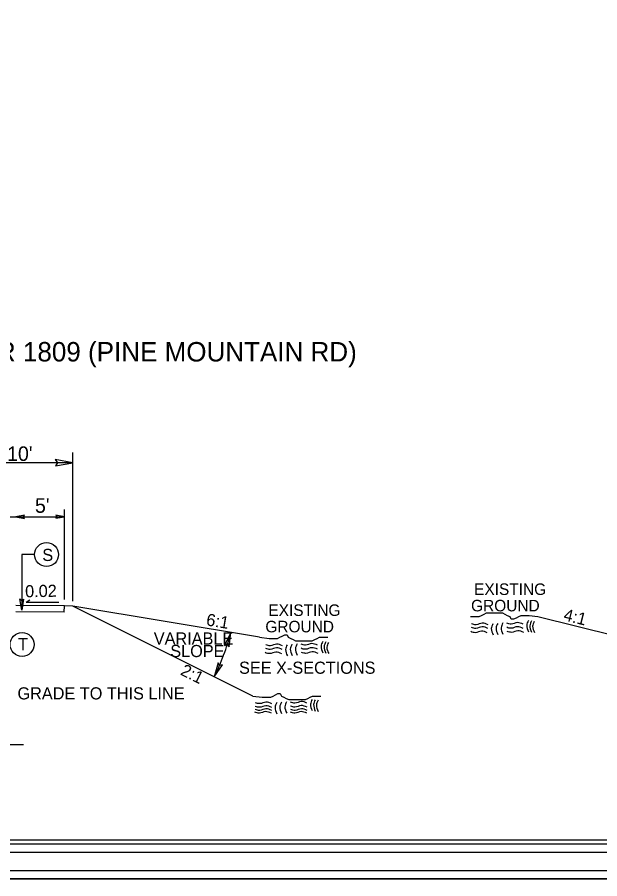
# Model space of a CAD drawing. Extents: x 2294455 to 2294795, y 719276 to 719941.
# Drawn here: x 2294590 to 2294664.8, y 719495.3 to 719606.2 of the extents above; entities that cross this region are included whole.
import ezdxf

# ---------------------------------------------------------------- set-up
doc = ezdxf.new("R2010")
doc.units = 0
for name, color, linetype in [('Default', 7, 'Continuous'), ('Old_Level_1', 7, 'Continuous'), ('Old_Level_11', 7, 'Continuous'), ('Old_Level_2', 7, 'Continuous'), ('Old_Level_3', 7, 'Continuous'), ('Sheet Cutting Line CELL', 7, 'Continuous'), ('Sheet Plot Border Inside CELL', 7, 'Continuous'), ('Sheet Plot Border Outside CELL', 7, 'Continuous'), ('Sheet Typical CELL', 7, 'Continuous'), ('Typical Hinge Slope Arterial CELL', 7, 'Continuous'), ('Typical ID Circle CELL', 7, 'Continuous'), ('Typical Terminator CELL', 7, 'Continuous'), ('Typical Text ID Circle CELL', 7, 'Continuous')]:
    doc.layers.add(name, color=color, linetype=linetype)

msp = doc.modelspace()

# ---------------------------------------------------------------- linework, layer by layer
at = {"layer": 'Default'}
msp.add_lwpolyline([(2294454.52, 719715.33), (2294794.52, 719715.33), (2294794.52, 719495.33), (2294454.52, 719495.33)], close=True, dxfattribs=at)
at = {"layer": 'Old_Level_1'}
for p, q in [((2294596.03, 719530.45), (2294589.78, 719530.49)), ((2294591.09, 719530.91), (2294591.59, 719531.22)), ((2294591.09, 719530.91), (2294595.3, 719530.91)), ((2294596.01, 719529.62), (2294596.03, 719530.45)), ((2294597.1, 719530.4), (2294596.03, 719530.45)), ((2294620.23, 719518.84), (2294597.1, 719530.4)), ((2294596.01, 719529.62), (2294589.78, 719529.66))]:
    msp.add_line(p, q, dxfattribs=at)
at = {"layer": 'Old_Level_11'}
for p, q in [((2294597.1, 719531.06), (2294597.1, 719550.17)), ((2294597.11, 719548.86), (2294581.48, 719548.86)), ((2294596.03, 719531.27), (2294596.03, 719542.83)), ((2294583.98, 719541.89), (2294596.03, 719541.89)), ((2294590.78, 719512.58), (2294528.76, 719512.58))]:
    msp.add_line(p, q, dxfattribs=at)
for points in [[(2294594.86, 719548.47), (2294597.11, 719548.86), (2294594.85, 719549.26), (2294595.14, 719548.86)], [(2294590.91, 719542.09), (2294589.78, 719541.89), (2294590.91, 719541.69), (2294590.77, 719541.89)], [(2294594.91, 719541.7), (2294596.03, 719541.89), (2294594.9, 719542.09), (2294595.05, 719541.89)], [(2294617.2, 719525.16), (2294617.41, 719527.02), (2294616.58, 719525.33), (2294616.96, 719525.46)], [(2294615.77, 719523.12), (2294615.28, 719521.32), (2294616.35, 719522.86), (2294615.96, 719522.78)]]:
    msp.add_lwpolyline(points, close=True, dxfattribs=at)
at = {"layer": 'Old_Level_2'}
for points in [[(2294650.48, 719528), (2294649.73, 719528.21), (2294648.94, 719528.01), (2294648.36, 719528.13)], [(2294650.48, 719528), (2294649.73, 719528.21), (2294648.94, 719528.01), (2294648.36, 719528.13)], [(2294651.1, 719528.14), (2294650.89, 719527.52), (2294651.12, 719526.7)], [(2294651.71, 719528.19), (2294651.5, 719527.57), (2294651.72, 719526.75)], [(2294652.36, 719528.24), (2294652.16, 719527.62), (2294652.38, 719526.8)], [(2294652.36, 719528.24), (2294652.16, 719527.62), (2294652.38, 719526.8)], [(2294654.99, 719528.07), (2294654.24, 719528.28), (2294653.45, 719528.08), (2294652.88, 719528.21)], [(2294654.99, 719528.07), (2294654.24, 719528.28), (2294653.45, 719528.08), (2294652.88, 719528.21)], [(2294655.66, 719528.55), (2294655.44, 719527.93), (2294655.67, 719527.11)], [(2294655.66, 719528.55), (2294655.44, 719527.93), (2294655.67, 719527.11)], [(2294656.05, 719528.51), (2294655.84, 719527.89), (2294656.07, 719527.06)], [(2294656.05, 719528.51), (2294655.84, 719527.89), (2294656.07, 719527.06)], [(2294656.41, 719528.44), (2294656.2, 719527.82), (2294656.43, 719527)], [(2294656.41, 719528.44), (2294656.2, 719527.82), (2294656.43, 719527)], [(2294650.38, 719526.98), (2294649.63, 719527.19), (2294648.84, 719526.99), (2294648.26, 719527.12)], [(2294650.38, 719526.98), (2294649.63, 719527.19), (2294648.84, 719526.99), (2294648.26, 719527.12)], [(2294650.46, 719527.52), (2294649.71, 719527.74), (2294648.92, 719527.54), (2294648.34, 719527.66)], [(2294650.46, 719527.52), (2294649.71, 719527.74), (2294648.92, 719527.54), (2294648.34, 719527.66)], [(2294655, 719527.54), (2294654.24, 719527.76), (2294653.45, 719527.55), (2294652.88, 719527.68)], [(2294655, 719527.54), (2294654.24, 719527.76), (2294653.45, 719527.55), (2294652.88, 719527.68)], [(2294655.06, 719527.02), (2294654.3, 719527.23), (2294653.51, 719527.03), (2294652.93, 719527.16)], [(2294655.06, 719527.02), (2294654.3, 719527.23), (2294653.51, 719527.03), (2294652.93, 719527.16)], [(2294624.02, 719524.82), (2294623.27, 719525.04), (2294622.48, 719524.84), (2294621.9, 719524.97)], [(2294624.02, 719524.82), (2294623.27, 719525.04), (2294622.48, 719524.84), (2294621.9, 719524.97)], [(2294624.04, 719525.3), (2294623.29, 719525.51), (2294622.5, 719525.31), (2294621.92, 719525.44)], [(2294624.04, 719525.3), (2294623.29, 719525.51), (2294622.5, 719525.31), (2294621.92, 719525.44)], [(2294624.66, 719525.44), (2294624.45, 719524.82), (2294624.68, 719524)], [(2294625.27, 719525.49), (2294625.06, 719524.87), (2294625.29, 719524.05)], [(2294625.27, 719525.49), (2294625.06, 719524.87), (2294625.29, 719524.05)], [(2294625.93, 719525.55), (2294625.72, 719524.93), (2294625.94, 719524.1)], [(2294625.93, 719525.55), (2294625.72, 719524.93), (2294625.94, 719524.1)], [(2294628.56, 719525.37), (2294627.81, 719525.58), (2294627.01, 719525.38), (2294626.44, 719525.51)], [(2294628.56, 719525.37), (2294627.81, 719525.58), (2294627.01, 719525.38), (2294626.44, 719525.51)], [(2294628.56, 719524.85), (2294627.81, 719525.06), (2294627.02, 719524.85), (2294626.44, 719524.98)], [(2294628.56, 719524.85), (2294627.81, 719525.06), (2294627.02, 719524.85), (2294626.44, 719524.98)], [(2294629.22, 719525.85), (2294629.01, 719525.23), (2294629.24, 719524.41)], [(2294629.22, 719525.85), (2294629.01, 719525.23), (2294629.24, 719524.41)], [(2294629.61, 719525.81), (2294629.4, 719525.19), (2294629.63, 719524.37)], [(2294629.61, 719525.81), (2294629.4, 719525.19), (2294629.63, 719524.37)], [(2294629.97, 719525.74), (2294629.76, 719525.12), (2294629.99, 719524.3)], [(2294629.97, 719525.74), (2294629.76, 719525.12), (2294629.99, 719524.3)], [(2294623.95, 719524.28), (2294623.19, 719524.49), (2294622.4, 719524.29), (2294621.83, 719524.42)], [(2294623.95, 719524.28), (2294623.19, 719524.49), (2294622.4, 719524.29), (2294621.83, 719524.42)], [(2294628.62, 719524.32), (2294627.87, 719524.53), (2294627.07, 719524.33), (2294626.5, 719524.46)], [(2294628.62, 719524.32), (2294627.87, 719524.53), (2294627.07, 719524.33), (2294626.5, 719524.46)], [(2294627.2, 719517.92), (2294626.45, 719518.13), (2294625.65, 719517.93), (2294625.08, 719518.06)], [(2294627.2, 719517.92), (2294626.45, 719518.13), (2294625.65, 719517.93), (2294625.08, 719518.06)], [(2294627.87, 719518.4), (2294627.65, 719517.78), (2294627.88, 719516.96)], [(2294628.25, 719518.36), (2294628.05, 719517.74), (2294628.27, 719516.91)], [(2294628.62, 719518.29), (2294628.41, 719517.67), (2294628.64, 719516.84)], [(2294622.67, 719517.37), (2294621.91, 719517.59), (2294621.12, 719517.39), (2294620.55, 719517.51)], [(2294622.67, 719517.37), (2294621.91, 719517.59), (2294621.12, 719517.39), (2294620.55, 719517.51)], [(2294622.67, 719516.98), (2294621.92, 719517.19), (2294621.12, 719516.99), (2294620.55, 719517.12)], [(2294622.67, 719516.98), (2294621.92, 719517.19), (2294621.12, 719516.99), (2294620.55, 719517.12)], [(2294622.69, 719517.85), (2294621.93, 719518.06), (2294621.14, 719517.86), (2294620.57, 719517.98)], [(2294623.31, 719517.99), (2294623.1, 719517.37), (2294623.33, 719516.55)], [(2294623.31, 719517.99), (2294623.1, 719517.37), (2294623.33, 719516.55)], [(2294623.92, 719518.04), (2294623.7, 719517.42), (2294623.93, 719516.6)], [(2294623.92, 719518.04), (2294623.7, 719517.42), (2294623.93, 719516.6)], [(2294624.57, 719518.09), (2294624.36, 719517.47), (2294624.59, 719516.65)], [(2294624.57, 719518.09), (2294624.36, 719517.47), (2294624.59, 719516.65)], [(2294627.21, 719517.39), (2294626.45, 719517.61), (2294625.66, 719517.4), (2294625.09, 719517.53)], [(2294627.21, 719517.39), (2294626.45, 719517.61), (2294625.66, 719517.4), (2294625.09, 719517.53)], [(2294627.23, 719516.98), (2294626.48, 719517.19), (2294625.68, 719516.99), (2294625.11, 719517.12)], [(2294627.23, 719516.98), (2294626.48, 719517.19), (2294625.68, 719516.99), (2294625.11, 719517.12)], [(2294622.63, 719516.62), (2294621.87, 719516.83), (2294621.08, 719516.63), (2294620.5, 719516.76)], [(2294627.19, 719516.62), (2294626.44, 719516.83), (2294625.64, 719516.63), (2294625.07, 719516.76)]]:
    msp.add_spline(points, degree=3, dxfattribs=at)
at = {"layer": 'Sheet Cutting Line CELL'}
msp.add_line((2294791.96, 719496.34), (2294455.16, 719496.34), dxfattribs=at)
at = {"layer": 'Sheet Plot Border Inside CELL'}
msp.add_lwpolyline([(2294790.42, 719710.84), (2294457.12, 719710.84), (2294457.12, 719499.82), (2294790.42, 719499.82)], close=True, dxfattribs=at)
at = {"layer": 'Sheet Plot Border Outside CELL'}
for points in [[(2294793.79, 719718.76), (2294456.99, 719718.76), (2294456.99, 719498.76), (2294793.79, 719498.76)], [(2294794.52, 719715.33), (2294454.52, 719715.33), (2294454.52, 719495.33), (2294794.52, 719495.33)]]:
    msp.add_lwpolyline(points, close=True, dxfattribs=at)
at = {"layer": 'Sheet Typical CELL'}
msp.add_lwpolyline([(2294787.92, 719710.33), (2294487.92, 719710.33), (2294487.92, 719500.33), (2294787.92, 719500.33)], close=True, dxfattribs=at)
at = {"layer": 'Typical Hinge Slope Arterial CELL'}
for p, q in [((2294621.11, 719526.4), (2294597.1, 719530.4)), ((2294666.89, 719526.53), (2294656.88, 719529.03))]:
    msp.add_line(p, q, dxfattribs=at)
for points in [[(2294656.88, 719529.03), (2294655.76, 719529.17), (2294655.45, 719529.17), (2294654.99, 719529.17), (2294654.68, 719529.17), (2294654.38, 719529.02), (2294654.07, 719528.86), (2294653.76, 719528.71), (2294653.45, 719528.71), (2294653.3, 719529.02), (2294652.99, 719529.17), (2294652.68, 719529.32), (2294652.37, 719529.48), (2294652.07, 719529.48), (2294651.76, 719529.48), (2294651.45, 719529.48), (2294651.14, 719529.48), (2294650.83, 719529.48), (2294650.53, 719529.48), (2294650.22, 719529.48), (2294649.91, 719529.32), (2294649.6, 719529.17), (2294649.29, 719529.02), (2294648.83, 719529.02), (2294648.52, 719529.02), (2294648.22, 719529.02)], [(2294621.11, 719526.4), (2294622.34, 719526.25), (2294622.65, 719526.25), (2294623.11, 719526.25), (2294623.42, 719526.25), (2294623.73, 719526.4), (2294624.03, 719526.55), (2294624.34, 719526.71), (2294624.65, 719526.71), (2294624.8, 719526.4), (2294625.11, 719526.25), (2294625.42, 719526.09), (2294625.73, 719525.94), (2294626.04, 719525.94), (2294626.34, 719525.94), (2294626.65, 719525.94), (2294626.96, 719525.94), (2294627.27, 719525.94), (2294627.58, 719525.94), (2294627.88, 719525.94), (2294628.19, 719526.09), (2294628.5, 719526.25), (2294628.81, 719526.4), (2294629.27, 719526.4), (2294629.58, 719526.4), (2294629.89, 719526.4)], [(2294620.23, 719518.84), (2294621.46, 719518.68), (2294621.77, 719518.68), (2294622.23, 719518.68), (2294622.54, 719518.68), (2294622.84, 719518.84), (2294623.15, 719518.99), (2294623.46, 719519.15), (2294623.77, 719519.15), (2294623.92, 719518.84), (2294624.23, 719518.68), (2294624.54, 719518.53), (2294624.85, 719518.38), (2294625.15, 719518.38), (2294625.46, 719518.38), (2294625.77, 719518.38), (2294626.08, 719518.38), (2294626.39, 719518.38), (2294626.69, 719518.38), (2294627, 719518.38), (2294627.31, 719518.53), (2294627.62, 719518.68), (2294627.93, 719518.84), (2294628.39, 719518.84), (2294628.7, 719518.84), (2294629, 719518.84)]]:
    msp.add_lwpolyline(points, dxfattribs=at)
msp.add_arc((2294589.39, 719534.26), 28.94, 333.4349, 345.5, dxfattribs=at)
at = {"layer": 'Typical ID Circle CELL'}
for p, q in [((2294590.53, 719537.04), (2294590.53, 719529.89)), ((2294592.19, 719537.04), (2294590.53, 719537.04))]:
    msp.add_line(p, q, dxfattribs=at)
for centre in [(2294593.73, 719537.04), (2294590.58, 719525.47)]:
    msp.add_circle(centre, 1.54, dxfattribs=at)
at = {"layer": 'Typical Terminator CELL'}
msp.add_lwpolyline([(2294590.78, 719531.32), (2294590.53, 719529.89), (2294590.28, 719531.33), (2294590.53, 719531.15)], close=True, dxfattribs=at)

# ---------------------------------------------------------------- texts
at = {"layer": 'Old_Level_1'}
for s, height, rotation, p in [('EXISTING', 1.484, 0, (2294648.68, 719531.84)), ('EXISTING', 1.484, 0, (2294622.24, 719529.14)), ('GROUND', 1.484, 0, (2294648.29, 719529.73)), ('6:1', 1.562, 350.5377, (2294614.17, 719527.94)), ('4:1', 1.562, 346.1434, (2294660.08, 719528.6)), ('GROUND', 1.484, 0, (2294621.85, 719527.03)), ('2:1', 1.562, 333.4349, (2294610.82, 719521.63)), ('SEE X-SECTIONS', 1.5625, 0, (2294618.47, 719521.7))]:
    msp.add_text(s, height=height, rotation=rotation, dxfattribs=at).set_placement(p)
at = {"layer": 'Old_Level_11'}
for s, p in [("10'", (2294588.66, 719549.08)), ("5'", (2294592.24, 719542.41))]:
    msp.add_text(s, height=1.875, dxfattribs=at).set_placement(p)
msp.add_text('GRADE TO THIS LINE', height=1.5625, rotation=360, dxfattribs=at).set_placement((2294589.99, 719518.4))
at = {"layer": 'Old_Level_3'}
for s, height, rotation, p in [('-Y38SW- SR 1809 (PINE MOUNTAIN RD)', 2.5, 360, (2294570.63, 719561.88)), ('0.02', 1.562, 1.1457, (2294590.99, 719531.53))]:
    msp.add_text(s, height=height, rotation=rotation, dxfattribs=at).set_placement(p)
at = {"layer": 'Typical Hinge Slope Arterial CELL'}
for s, p in [('VARIABLE ', (2294607.51, 719525.46)), ('SLOPE', (2294609.63, 719523.85))]:
    msp.add_text(s, height=1.562, dxfattribs=at).set_placement(p)
at = {"layer": 'Typical Text ID Circle CELL'}
for s, p in [('S', (2294593.18, 719536.21)), ('T', (2294590.06, 719524.73))]:
    msp.add_text(s, height=1.56, dxfattribs=at).set_placement(p)

doc.saveas('drawing.dxf')
